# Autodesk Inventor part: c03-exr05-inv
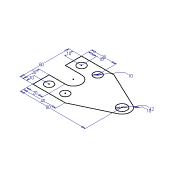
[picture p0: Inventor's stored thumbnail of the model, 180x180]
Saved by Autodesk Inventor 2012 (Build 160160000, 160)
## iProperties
Shininess: 64.0
Length Units: 11269
Angle Units: 11279
Time Units: 11290
Mass Units: 11283
Length Display Precision: 3
Angle Display Precision: 2
Compacted: True
Created: 2002-02
Part Number: c03-exr05-inv
Document SubType Name: Modeling
Density: 1 g/cm^3
Material: Default
Density: 0.0
Volumn: 0.0
Area: 0.0
PropertySet Name: Model Information
Control State: 0
Master: False
Checked Out: False
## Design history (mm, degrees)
sketch "Sketch1"
  geometry: L1 (-41.454, 11.298)-(-21.454, 11.298); L2 (-21.454, -8.702)-(-41.454, -8.702); L3 (-41.454, -8.702)-(-41.454, -28.702); L4 (-41.454, -28.702)-(-1.454, -28.702); L5 (-1.454, -28.702)-(42.825, -7.74); L6 (42.825, 10.337)-(-1.454, 31.298); L7 (-1.454, 31.298)-(-41.454, 31.298); L8 (-41.454, 31.298)-(-41.454, 11.298); C1 r 5 at (-31.454, 21.298); C2 r 5 at (-11.454, 21.298); C3 r 5 at (-31.454, -18.702); C4 r 5 at (-11.454, -18.702); C5 r 6 at (38.546, 1.298); A1 r 10 centre (-21.454, 1.298) between (-21.454, -8.702) and (-21.454, 11.298); A2 r 10 centre (38.546, 1.298) between (42.825, -7.74) and (42.825, 10.337)
  constraints: 16 end point, 7 centre point, 4 equal length, 4 point on circle, 4 tangent, 3 equal radius, 3 parallel, 2 vertical alignment, 1 coincident, 1 collinear, 1 horizontal, 1 horizontal alignment, 1 perpendicular
  dimensions: "d0" = 20 distance of L2.end L3.end; "d2" = 80 distance from line of A2.centre L3; "d3" = 10 radius of A2; "d4" = 40 distance of L3.end L4.end; "d5" = 20 distance of L2.start L2.end; "d6" = 60 distance between parallel lines of L4 L7; "d7" = 10 diameter of C2; "d8" = 10 distance from line of L8 C1.centre; "d9" = 30 distance from line of L8 C2.centre; "d10" = 10 distance from line of L7 C1.centre; "d11" = 10 distance from line of L4 C3.centre; "d12" = 12 diameter of C5
